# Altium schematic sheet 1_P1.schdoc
size 307 x 218 mm; Symbol: Drawing-Symbol_A4; Device: Drawing-Symbol_A4; @Project Name: clockX-V1; @Page Count: 1; @Update Date: 2026-02-05; @Create Date: 2026-02-05; @Schematic Name: Schematic1; @Page No: 1; @Page Name: P1; Company: EasyEDA.com; Version: V1.0; Page Size: A4; @Create Time: 14:57:27; @Update Time: 17:14:36; Width: 1170; Height: 825; Region Start: 1; X Region Count: 6; Y Region Count: 4; Blade Width: 10; Title Block Position: 3; @Board Name: Board1
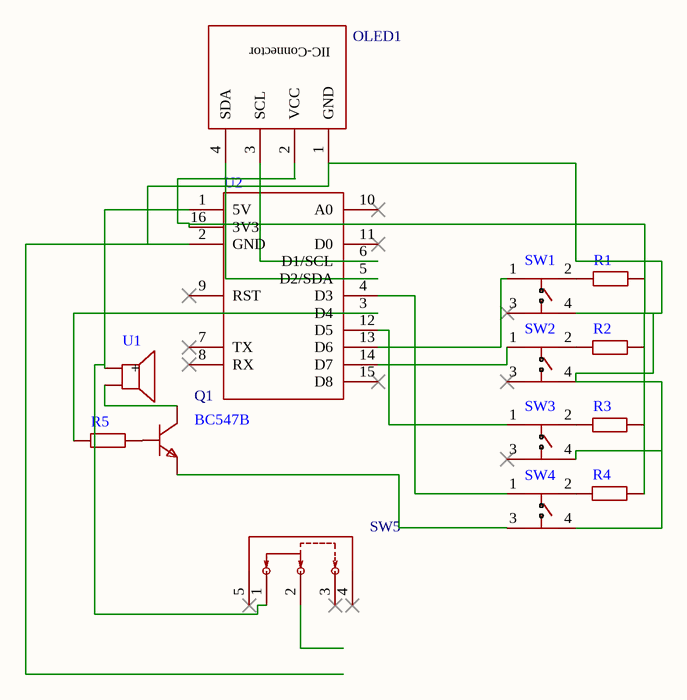
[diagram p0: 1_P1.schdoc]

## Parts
OLED1  0.96OLED_4P_MODULE_JX  [0.96OLED_4P]  (value not drawn)
Q1  BC547B  [TO-92-3_L4.9-W3.7-P1.27-L]
R1  (no value)  [Resistor 1/8w 7mm metal film]
R2  (no value)  [Resistor 1/8w 7mm metal film]
R3  (no value)  [Resistor 1/8w 7mm metal film]
R4  (no value)  [Resistor 1/8w 7mm metal film]
R5  (no value)  [Resistor 1/8w 7mm metal film]
SW1  MLD-TS-6X6X5-J  [SW-TH_4P-L6.0-W6.0-P4.50-LS6.5]  (value not drawn)
SW2  MLD-TS-6X6X5-J  [SW-TH_4P-L6.0-W6.0-P4.50-LS6.5]  (value not drawn)
SW3  MLD-TS-6X6X5-J  [SW-TH_4P-L6.0-W6.0-P4.50-LS6.5]  (value not drawn)
SW4  MLD-TS-6X6X5-J  [SW-TH_4P-L6.0-W6.0-P4.50-LS6.5]  (value not drawn)
SW5  SK12D07VG4  [SW-TH_SK12D07VG4]  (value not drawn)
U1  _x001F_BEEF-12095  [BUZ-TH_BD12.0-P7.60-D0.6-FD]  (value not drawn)
U2  (no value)  [WEMOS D1 MINI]

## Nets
NetOLED1_1: OLED1.1(GND) SW1.4 SW2.4 SW3.4 SW4.4 U2.2(GND)
NetOLED1_2: OLED1.2(VCC) R1.2 R2.2 R3.2 R4.2 U2.16(3V3)
NetOLED1_3: OLED1.3(SCL) U2.6(D1/SCL)
NetOLED1_4: OLED1.4(SDA) U2.5(D2/SDA)
NetQ1_1: Q1.1(C) U1.2
NetQ1_2: Q1.2(B) R5.2
NetQ1_3: Q1.3(E) SW4.3
NetR1_1: R1.1 SW1.2
NetR2_1: R2.1 SW2.2
NetR3_1: R3.1 SW3.2
NetR4_1: R4.1 SW4.2
NetR5_1: R5.1 U2.3(D4)
NetSW1_1: SW1.1 U2.13(D6)
NetSW2_1: SW2.1 U2.14(D7)
NetSW3_1: SW3.1 U2.12(D5)
NetSW4_1: SW4.1 U2.4(D3)
NetSW5_1: SW5.1 U1.1(+) U2.1(5V)

Not connected (* = marked no-connect by the designer): SW1 3*; SW2 3*; SW3 3*; SW5 2 3* 4* 5*; U2 7(TX)* 8(RX)* 9(RST)* 10(A0)* 11(D0)* 15(D8)*

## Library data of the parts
OLED1 = 0.96OLED_4P_MODULE_JX: Add into BOM: yes
Q1 = BC547B_C719806: Manufacturer: onsemi(安森美); Add into BOM: yes; DC Current Gain (hFE@Ic,Vce): 200@2mA,5V; Transition Frequency (fT): 300MHz; Collector Cut-Off Current (Icbo): 15nA; Collector-Emitter Saturation Voltage (VCE(sat)@Ic,Ib): 600mV@5mA,100mA
R1-R5 = resistor: Manufacturer: UNI-ROYAL(Uniroyal Elec); Manufacturer Part: 1206W4F1002T5E; Resistance: 10KΩ; Add into BOM: yes
SW1-SW4 = MLD-TS-6X6X5-J: Manufacturer: Minlenda(敏连达); Add into BOM: yes
SW5 = SK12D07VG4: Manufacturer: SHOU HAN(首韩); Add into BOM: yes; Circuit: SPDT; Actuator Style: Rectangular Columnar; Switch Height: 8.8mm; Current Rating: 500mA; Voltage Rating: 50V; Life: 5,000 cycles
U1 = _x001F_BEEF-12095: Add into BOM: yes
U2 = WEMOS D1 MINI: Add into BOM: yes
